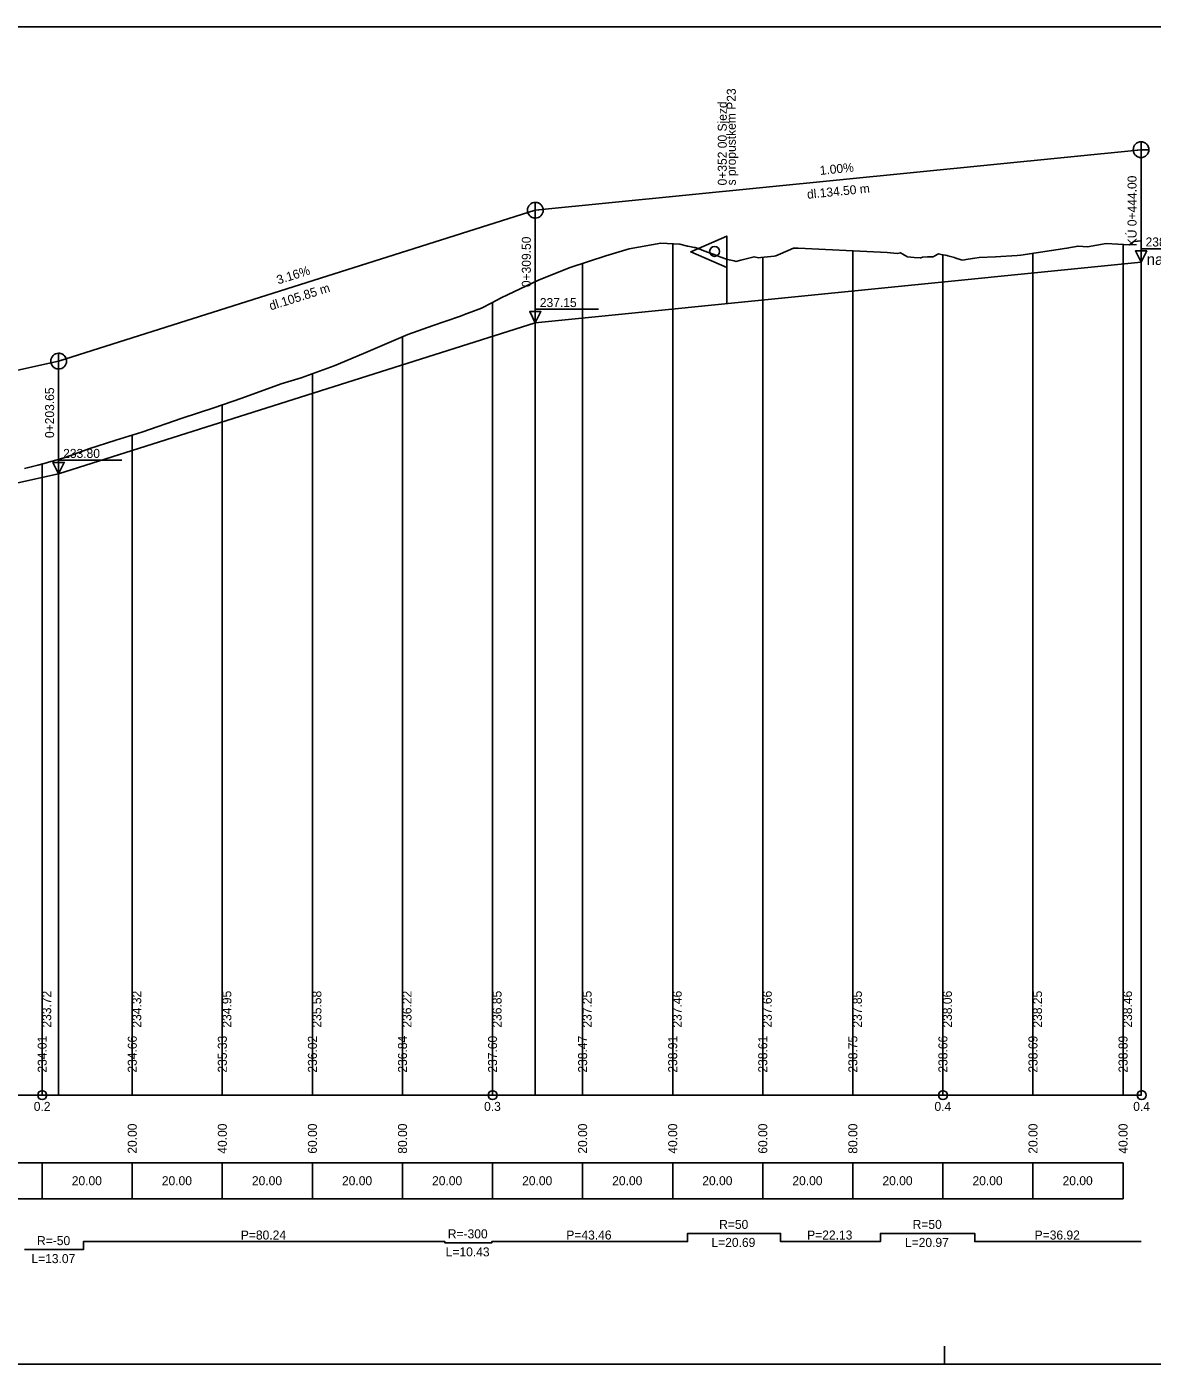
# Model space of a CAD drawing. Extents: x -578560 to -577720, y -1159785 to -1159488.
# Drawn here: x -578133.4 to -577883.5, y -1159784.6 to -1159487.6 of the extents above; entities that cross this region are included whole.
import ezdxf

# ---------------------------------------------------------------- set-up
doc = ezdxf.new("R2010")
doc.units = 0
for name, color, linetype in [('11', 7, 'Continuous'), ('14', 7, 'Continuous'), ('16', 7, 'Continuous'), ('4', 7, 'Continuous'), ('46', 7, 'Continuous'), ('56', 7, 'Continuous'), ('8', 7, 'Continuous'), ('Popis PP', 7, 'Continuous'), ('Rámy', 7, 'Continuous')]:
    doc.layers.add(name, color=color, linetype=linetype)

msp = doc.modelspace()

# ---------------------------------------------------------------- linework, layer by layer
for p, q in [((-577990.01, -1159724.86), (-577990.01, -1159535.76)), ((-577950.01, -1159724.86), (-577950.01, -1159537.36)), ((-577930.01, -1159724.86), (-577930.01, -1159538.26)), ((-577910.01, -1159724.86), (-577910.01, -1159537.96)), ((-577890.01, -1159724.86), (-577890.01, -1159535.96)), ((-578010.01, -1159724.86), (-578010.01, -1159540.16)), ((-577970.01, -1159724.86), (-577970.01, -1159538.76)), ((-578030.01, -1159724.86), (-578030.01, -1159548.86)), ((-578050.01, -1159724.86), (-578050.01, -1159556.46)), ((-578070.01, -1159724.86), (-578070.01, -1159564.66)), ((-578090.01, -1159724.86), (-578090.01, -1159571.56)), ((-578110.01, -1159724.86), (-578110.01, -1159578.26)), ((-578130.01, -1159724.86), (-578130.01, -1159584.76)), ((-578330.01, -1159739.86), (-577890.01, -1159739.86)), ((-578130.01, -1159739.86), (-578130.01, -1159747.86)), ((-578110.01, -1159739.86), (-578110.01, -1159747.86)), ((-578090.01, -1159739.86), (-578090.01, -1159747.86)), ((-578070.01, -1159739.86), (-578070.01, -1159747.86)), ((-578050.01, -1159739.86), (-578050.01, -1159747.86)), ((-578030.01, -1159739.86), (-578030.01, -1159747.86)), ((-578010.01, -1159739.86), (-578010.01, -1159747.86)), ((-577990.01, -1159739.86), (-577990.01, -1159747.86)), ((-577970.01, -1159739.86), (-577970.01, -1159747.86)), ((-577950.01, -1159739.86), (-577950.01, -1159747.86)), ((-577930.01, -1159739.86), (-577930.01, -1159747.86)), ((-577910.01, -1159739.86), (-577910.01, -1159747.86)), ((-577890.01, -1159739.86), (-577890.01, -1159747.86)), ((-578330.01, -1159747.86), (-577890.01, -1159747.86))]:
    msp.add_line(p, q)
for points in [[(-578133.91, -1159585.69), (-578132.49, -1159585.37), (-578132.45, -1159585.37), (-578131, -1159585), (-578129.55, -1159584.61), (-578128.1, -1159584.19), (-578126.65, -1159583.76), (-578125.2, -1159583.31), (-578123.74, -1159582.83), (-578122.76, -1159582.49), (-578122.29, -1159582.32), (-578120.84, -1159581.78), (-578119.62, -1159581.31), (-578113.66, -1159579.38), (-578107.91, -1159577.63), (-578098.9, -1159574.5), (-578091.91, -1159572.26), (-578085.69, -1159570.07), (-578076.93, -1159566.94), (-578072.5, -1159565.58), (-578065.19, -1159562.91), (-578058.68, -1159560.19), (-578048.83, -1159555.98), (-578043.16, -1159553.93), (-578040.6, -1159553.05), (-578037.13, -1159551.85), (-578036.2, -1159551.53), (-578033.65, -1159550.56), (-578032.44, -1159550.09), (-578030.18, -1159548.9), (-578028.11, -1159547.81), (-578019.66, -1159543.8), (-578012.74, -1159541.07), (-578004.83, -1159538.49), (-577999.68, -1159536.96), (-577992.64, -1159535.69), (-577988.46, -1159535.87), (-577986.72, -1159536.31), (-577986.24, -1159536.44), (-577985.24, -1159536.62), (-577985.04, -1159536.66), (-577983.77, -1159537.11), (-577983.45, -1159537.22), (-577982.29, -1159537.65), (-577980.81, -1159538.2), (-577979.33, -1159538.76), (-577978.06, -1159539.24), (-577977.86, -1159539.29), (-577976.38, -1159539.63), (-577975.99, -1159539.72), (-577974.9, -1159539.45), (-577973.42, -1159539.06), (-577971.95, -1159538.67), (-577971.95, -1159538.67), (-577970.96, -1159538.91), (-577970.47, -1159538.85), (-577968.99, -1159538.68), (-577967.51, -1159538.53), (-577967.14, -1159538.5), (-577966.04, -1159538.01), (-577963.17, -1159536.76), (-577962.18, -1159536.78), (-577943.9, -1159537.65), (-577942.4, -1159537.74), (-577940.91, -1159537.87), (-577940.04, -1159537.96), (-577939.44, -1159537.8), (-577939.41, -1159537.82), (-577938.88, -1159538.15), (-577938.01, -1159538.66), (-577937.91, -1159538.69), (-577937.89, -1159538.69), (-577936.41, -1159538.82), (-577935.04, -1159538.96), (-577934.91, -1159538.92), (-577934.51, -1159538.77), (-577933.42, -1159538.72), (-577932.12, -1159538.67), (-577931.92, -1159538.56), (-577931, -1159538.07), (-577930.42, -1159538.17), (-577929.1, -1159538.42), (-577928.92, -1159538.46), (-577927.43, -1159538.88), (-577927.36, -1159538.9), (-577925.93, -1159539.36), (-577925.68, -1159539.44), (-577924.43, -1159539.25), (-577922.93, -1159539.02), (-577921.96, -1159538.88), (-577918.31, -1159538.7), (-577913.49, -1159538.42), (-577912.71, -1159538.33), (-577902.47, -1159536.79), (-577900.01, -1159536.32), (-577897.93, -1159536.51), (-577893.75, -1159535.74), (-577888.56, -1159536.01), (-577887.58, -1159535.31), (-577886.01, -1159535.12)], [(-578133.91, -1159759.16), (-578120.84, -1159759.16), (-578120.84, -1159757.36), (-578040.6, -1159757.36), (-578040.6, -1159757.66), (-578030.18, -1159757.66), (-578030.18, -1159757.36), (-577986.72, -1159757.36), (-577986.72, -1159755.56), (-577966.04, -1159755.56), (-577966.04, -1159757.36), (-577943.9, -1159757.36), (-577943.9, -1159755.56), (-577922.93, -1159755.56), (-577922.93, -1159757.36), (-577886.01, -1159757.36)]]:
    msp.add_lwpolyline(points)
for centre, radius in [((-577980.71, -1159537.51), 1.09), ((-578130.01, -1159724.86), 1), ((-578030.01, -1159724.86), 1), ((-577930.01, -1159724.86), 1), ((-577885.88, -1159724.86), 1)]:
    msp.add_circle(centre, radius)
at = {"layer": '14'}
for p, q in [((-578020.51, -1159528.36), (-577886.01, -1159514.91)), ((-577886.01, -1159514.91), (-577886.01, -1159724.86)), ((-578126.36, -1159561.86), (-578020.51, -1159528.36)), ((-578020.51, -1159528.36), (-578020.51, -1159724.86)), ((-578020.51, -1159553.36), (-577886.01, -1159539.91)), ((-578020.51, -1159553.36), (-577886.01, -1159539.91)), ((-578020.51, -1159553.36), (-577886.01, -1159539.91)), ((-578126.36, -1159586.86), (-578020.51, -1159553.36)), ((-578126.36, -1159586.86), (-578020.51, -1159553.36)), ((-578126.36, -1159586.86), (-578020.51, -1159553.36)), ((-578165.01, -1159570.52), (-578126.36, -1159561.86)), ((-578126.36, -1159561.86), (-578126.36, -1159724.86)), ((-578165.01, -1159595.52), (-578126.36, -1159586.86)), ((-578165.01, -1159595.52), (-578126.36, -1159586.86)), ((-578165.01, -1159595.52), (-578126.36, -1159586.86))]:
    msp.add_line(p, q, dxfattribs=at)
at = {"layer": '46'}
for points in [[(-577886.01, -1159514.91), (-577886.01, -1159513.16), (-577885.9, -1159513.16), (-577885.78, -1159513.17), (-577885.67, -1159513.19), (-577885.56, -1159513.22), (-577885.46, -1159513.25), (-577885.35, -1159513.29), (-577885.25, -1159513.33), (-577885.15, -1159513.38), (-577885.05, -1159513.44), (-577884.96, -1159513.51), (-577884.87, -1159513.58), (-577884.79, -1159513.65), (-577884.71, -1159513.73), (-577884.64, -1159513.82), (-577884.57, -1159513.91), (-577884.51, -1159514), (-577884.46, -1159514.1), (-577884.41, -1159514.2), (-577884.37, -1159514.3), (-577884.33, -1159514.41), (-577884.3, -1159514.52), (-577884.28, -1159514.63), (-577884.27, -1159514.74), (-577884.26, -1159514.85), (-577884.26, -1159514.91), (-577886.01, -1159514.91), (-577886.01, -1159516.66), (-577886.12, -1159516.66), (-577886.23, -1159516.64), (-577886.34, -1159516.63), (-577886.45, -1159516.6), (-577886.56, -1159516.57), (-577886.67, -1159516.53), (-577886.77, -1159516.49), (-577886.87, -1159516.43), (-577886.96, -1159516.38), (-577887.06, -1159516.31), (-577887.14, -1159516.24), (-577887.23, -1159516.17), (-577887.3, -1159516.09), (-577887.38, -1159516), (-577887.44, -1159515.91), (-577887.51, -1159515.82), (-577887.56, -1159515.72), (-577887.61, -1159515.62), (-577887.65, -1159515.51), (-577887.69, -1159515.41), (-577887.71, -1159515.3), (-577887.74, -1159515.19), (-577887.75, -1159515.08)], [(-578020.51, -1159528.36), (-578020.51, -1159526.61), (-578020.4, -1159526.61), (-578020.28, -1159526.62), (-578020.17, -1159526.64), (-578020.06, -1159526.67), (-578019.96, -1159526.7), (-578019.85, -1159526.74), (-578019.75, -1159526.78), (-578019.65, -1159526.83), (-578019.55, -1159526.89), (-578019.46, -1159526.96), (-578019.37, -1159527.03), (-578019.29, -1159527.1), (-578019.21, -1159527.18), (-578019.14, -1159527.27), (-578019.07, -1159527.36), (-578019.01, -1159527.45), (-578018.96, -1159527.55), (-578018.91, -1159527.65), (-578018.87, -1159527.75), (-578018.83, -1159527.86), (-578018.8, -1159527.97), (-578018.78, -1159528.08), (-578018.77, -1159528.18), (-578020.51, -1159528.36), (-578020.51, -1159530.11), (-578020.62, -1159530.11), (-578020.73, -1159530.09), (-578020.84, -1159530.08), (-578020.95, -1159530.05), (-578021.06, -1159530.02), (-578021.17, -1159529.98), (-578021.27, -1159529.94), (-578021.37, -1159529.88), (-578021.46, -1159529.83), (-578021.56, -1159529.76), (-578021.64, -1159529.69), (-578021.73, -1159529.62), (-578021.8, -1159529.54), (-578021.88, -1159529.45), (-578021.94, -1159529.36), (-578022.01, -1159529.27), (-578022.06, -1159529.17), (-578022.11, -1159529.07), (-578022.15, -1159528.96), (-578022.18, -1159528.89)], [(-577886.01, -1159539.91), (-577887.26, -1159537.41), (-577884.76, -1159537.41)], [(-578020.51, -1159553.36), (-578021.76, -1159550.86), (-578019.26, -1159550.86)], [(-578126.36, -1159561.86), (-578126.36, -1159560.11), (-578126.24, -1159560.11), (-578126.13, -1159560.12), (-578126.02, -1159560.14), (-578125.91, -1159560.17), (-578125.8, -1159560.2), (-578125.7, -1159560.24), (-578125.6, -1159560.28), (-578125.5, -1159560.33), (-578125.4, -1159560.39), (-578125.31, -1159560.46), (-578125.22, -1159560.53), (-578125.14, -1159560.6), (-578125.06, -1159560.68), (-578124.99, -1159560.77), (-578124.92, -1159560.86), (-578124.86, -1159560.95), (-578124.8, -1159561.05), (-578124.76, -1159561.15), (-578124.71, -1159561.25), (-578124.69, -1159561.33), (-578126.36, -1159561.86), (-578126.36, -1159563.61), (-578126.47, -1159563.61), (-578126.58, -1159563.59), (-578126.69, -1159563.58), (-578126.8, -1159563.55), (-578126.91, -1159563.52), (-578127.01, -1159563.48), (-578127.12, -1159563.44), (-578127.22, -1159563.38), (-578127.31, -1159563.33), (-578127.4, -1159563.26), (-578127.49, -1159563.19), (-578127.57, -1159563.12), (-578127.65, -1159563.04), (-578127.72, -1159562.95), (-578127.79, -1159562.86), (-578127.85, -1159562.77), (-578127.91, -1159562.67), (-578127.96, -1159562.57), (-578128, -1159562.46), (-578128.03, -1159562.36), (-578128.06, -1159562.25), (-578128.06, -1159562.24)], [(-578126.36, -1159586.86), (-578127.61, -1159584.36), (-578125.11, -1159584.36)]]:
    msp.add_lwpolyline(points, close=True, dxfattribs=at)
for centre in [(-577886.01, -1159514.91), (-578020.51, -1159528.36), (-578126.36, -1159561.86)]:
    msp.add_circle(centre, 1.75, dxfattribs=at)
at = {"layer": '56'}
msp.add_line((-578330.01, -1159724.86), (-577885.88, -1159724.86), dxfattribs=at)
at = {"layer": '8'}
for p, q in [((-577886.01, -1159539.91), (-577886.01, -1159536.91)), ((-577886.01, -1159536.91), (-577872.01, -1159536.91)), ((-578020.51, -1159553.36), (-578020.51, -1159550.36)), ((-578020.51, -1159550.36), (-578006.51, -1159550.36)), ((-578126.36, -1159586.86), (-578126.36, -1159583.86)), ((-578126.36, -1159583.86), (-578112.36, -1159583.86))]:
    msp.add_line(p, q, dxfattribs=at)
at = {"layer": 'Popis PP'}
msp.add_lwpolyline([(-577978.01, -1159549.11), (-577978.01, -1159534.11), (-577986.01, -1159537.61), (-577978.01, -1159541.11)], dxfattribs=at)
at = {"layer": 'Rámy'}
msp.add_line((-577929.62, -1159784.61), (-577929.62, -1159780.61), dxfattribs=at)
msp.add_lwpolyline([(-578559.62, -1159487.61), (-577719.62, -1159487.61), (-577719.62, -1159784.61), (-578559.62, -1159784.61)], close=True, dxfattribs=at)

# ---------------------------------------------------------------- texts
for s, p in [('s propustkem P23', (-577976, -1159522.85)), ('0+352 00 Sjezd ', (-577978, -1159522.85)), ('233.72', (-578128.01, -1159709.86)), ('234.32', (-578108.01, -1159709.86)), ('234.95', (-578088.01, -1159709.86)), ('235.58', (-578068.01, -1159709.86)), ('236.22', (-578048.01, -1159709.86)), ('236.85', (-578028.01, -1159709.86)), ('237.25', (-578008.01, -1159709.86)), ('237.46', (-577988.01, -1159709.86)), ('237.66', (-577968.01, -1159709.86)), ('237.85', (-577948.01, -1159709.86)), ('238.06', (-577928.01, -1159709.86)), ('238.25', (-577908.01, -1159709.86)), ('238.46', (-577888.01, -1159709.86)), ('234.01', (-578129.01, -1159719.86)), ('234.66', (-578109.01, -1159719.86)), ('235.33', (-578089.01, -1159719.86)), ('236.02', (-578069.01, -1159719.86)), ('236.84', (-578049.01, -1159719.86)), ('237.60', (-578029.01, -1159719.86)), ('238.47', (-578009.01, -1159719.86)), ('238.91', (-577989.01, -1159719.86)), ('238.61', (-577969.01, -1159719.86)), ('238.75', (-577949.01, -1159719.86)), ('238.66', (-577929.01, -1159719.86)), ('238.69', (-577909.01, -1159719.86)), ('238.89', (-577889.01, -1159719.86)), ('20.00', (-578109.01, -1159737.86)), ('40.00', (-578089.01, -1159737.86)), ('60.00', (-578069.01, -1159737.86)), ('80.00', (-578049.01, -1159737.86)), ('20.00', (-578009.01, -1159737.86)), ('40.00', (-577989.01, -1159737.86)), ('60.00', (-577969.01, -1159737.86)), ('80.00', (-577949.01, -1159737.86)), ('20.00', (-577909.01, -1159737.86)), ('40.00', (-577889.01, -1159737.86))]:
    msp.add_text(s, height=2, rotation=90).set_placement(p)
for s, p in [('0.2', (-578131.88, -1159728.36)), ('0.3', (-578031.89, -1159728.36)), ('0.4', (-577931.88, -1159728.36)), ('0.4', (-577887.75, -1159728.36)), ('20.00', (-578123.44, -1159744.86)), ('20.00', (-578103.44, -1159744.86)), ('20.00', (-578083.44, -1159744.86)), ('20.00', (-578063.44, -1159744.86)), ('20.00', (-578043.44, -1159744.86)), ('20.00', (-578023.44, -1159744.86)), ('20.00', (-578003.44, -1159744.86)), ('20.00', (-577983.44, -1159744.86)), ('20.00', (-577963.44, -1159744.86)), ('20.00', (-577943.44, -1159744.86)), ('20.00', (-577923.44, -1159744.86)), ('20.00', (-577903.44, -1159744.86))]:
    msp.add_text(s, height=2).set_placement(p)
at = {"layer": '11'}
for s, p in [('P=80.24', (-578085.9, -1159756.92)), ('R=-300', (-578039.94, -1159756.66)), ('P=43.46', (-578013.63, -1159756.92)), ('R=50', (-577979.69, -1159754.56)), ('P=22.13', (-577960.15, -1159756.92)), ('R=50', (-577936.73, -1159754.56)), ('P=36.92', (-577909.64, -1159756.92)), ('R=-50', (-578131.15, -1159758.16)), ('L=20.69', (-577981.4, -1159758.56)), ('L=20.97', (-577938.44, -1159758.56)), ('L=13.07', (-578132.4, -1159762.16)), ('L=10.43', (-578040.41, -1159760.66))]:
    msp.add_text(s, height=2, dxfattribs=at).set_placement(p)
at = {"layer": '16'}
for s, rotation, p in [('1.00%', 5.7106, (-577957.26, -1159520.53)), ('dl.134.50 m', 5.7106, (-577960.08, -1159525.83)), ('KÚ 0+444.00', 90, (-577887.01, -1159536.36)), ('0+309.50', 90, (-578021.51, -1159545.44)), ('3.16%', 17.5622, (-578077.58, -1159544.85)), ('dl.105.85 m', 17.5622, (-578079.25, -1159550.62)), ('0+203.65', 90, (-578127.36, -1159578.94))]:
    msp.add_text(s, height=2, rotation=rotation, dxfattribs=at).set_placement(p)
for s, p in [('238.49', (-577885.01, -1159536.41)), ('237.15', (-578019.51, -1159549.86)), ('233.80', (-578125.36, -1159583.36))]:
    msp.add_text(s, height=2, dxfattribs=at).set_placement(p)
at = {"layer": '4'}
msp.add_text('napojení na zpevněnou', height=2.5, dxfattribs=at).set_placement((-577884.77, -1159540.52))

doc.saveas('drawing.dxf')
